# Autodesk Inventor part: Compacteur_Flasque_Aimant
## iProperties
Created: 2008-12
Part Number: Compacteur_Flasque_Aimant
Document SubType Name: Modeling
Designer: claivier
Author: claivier
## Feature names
1. Extrusion1
